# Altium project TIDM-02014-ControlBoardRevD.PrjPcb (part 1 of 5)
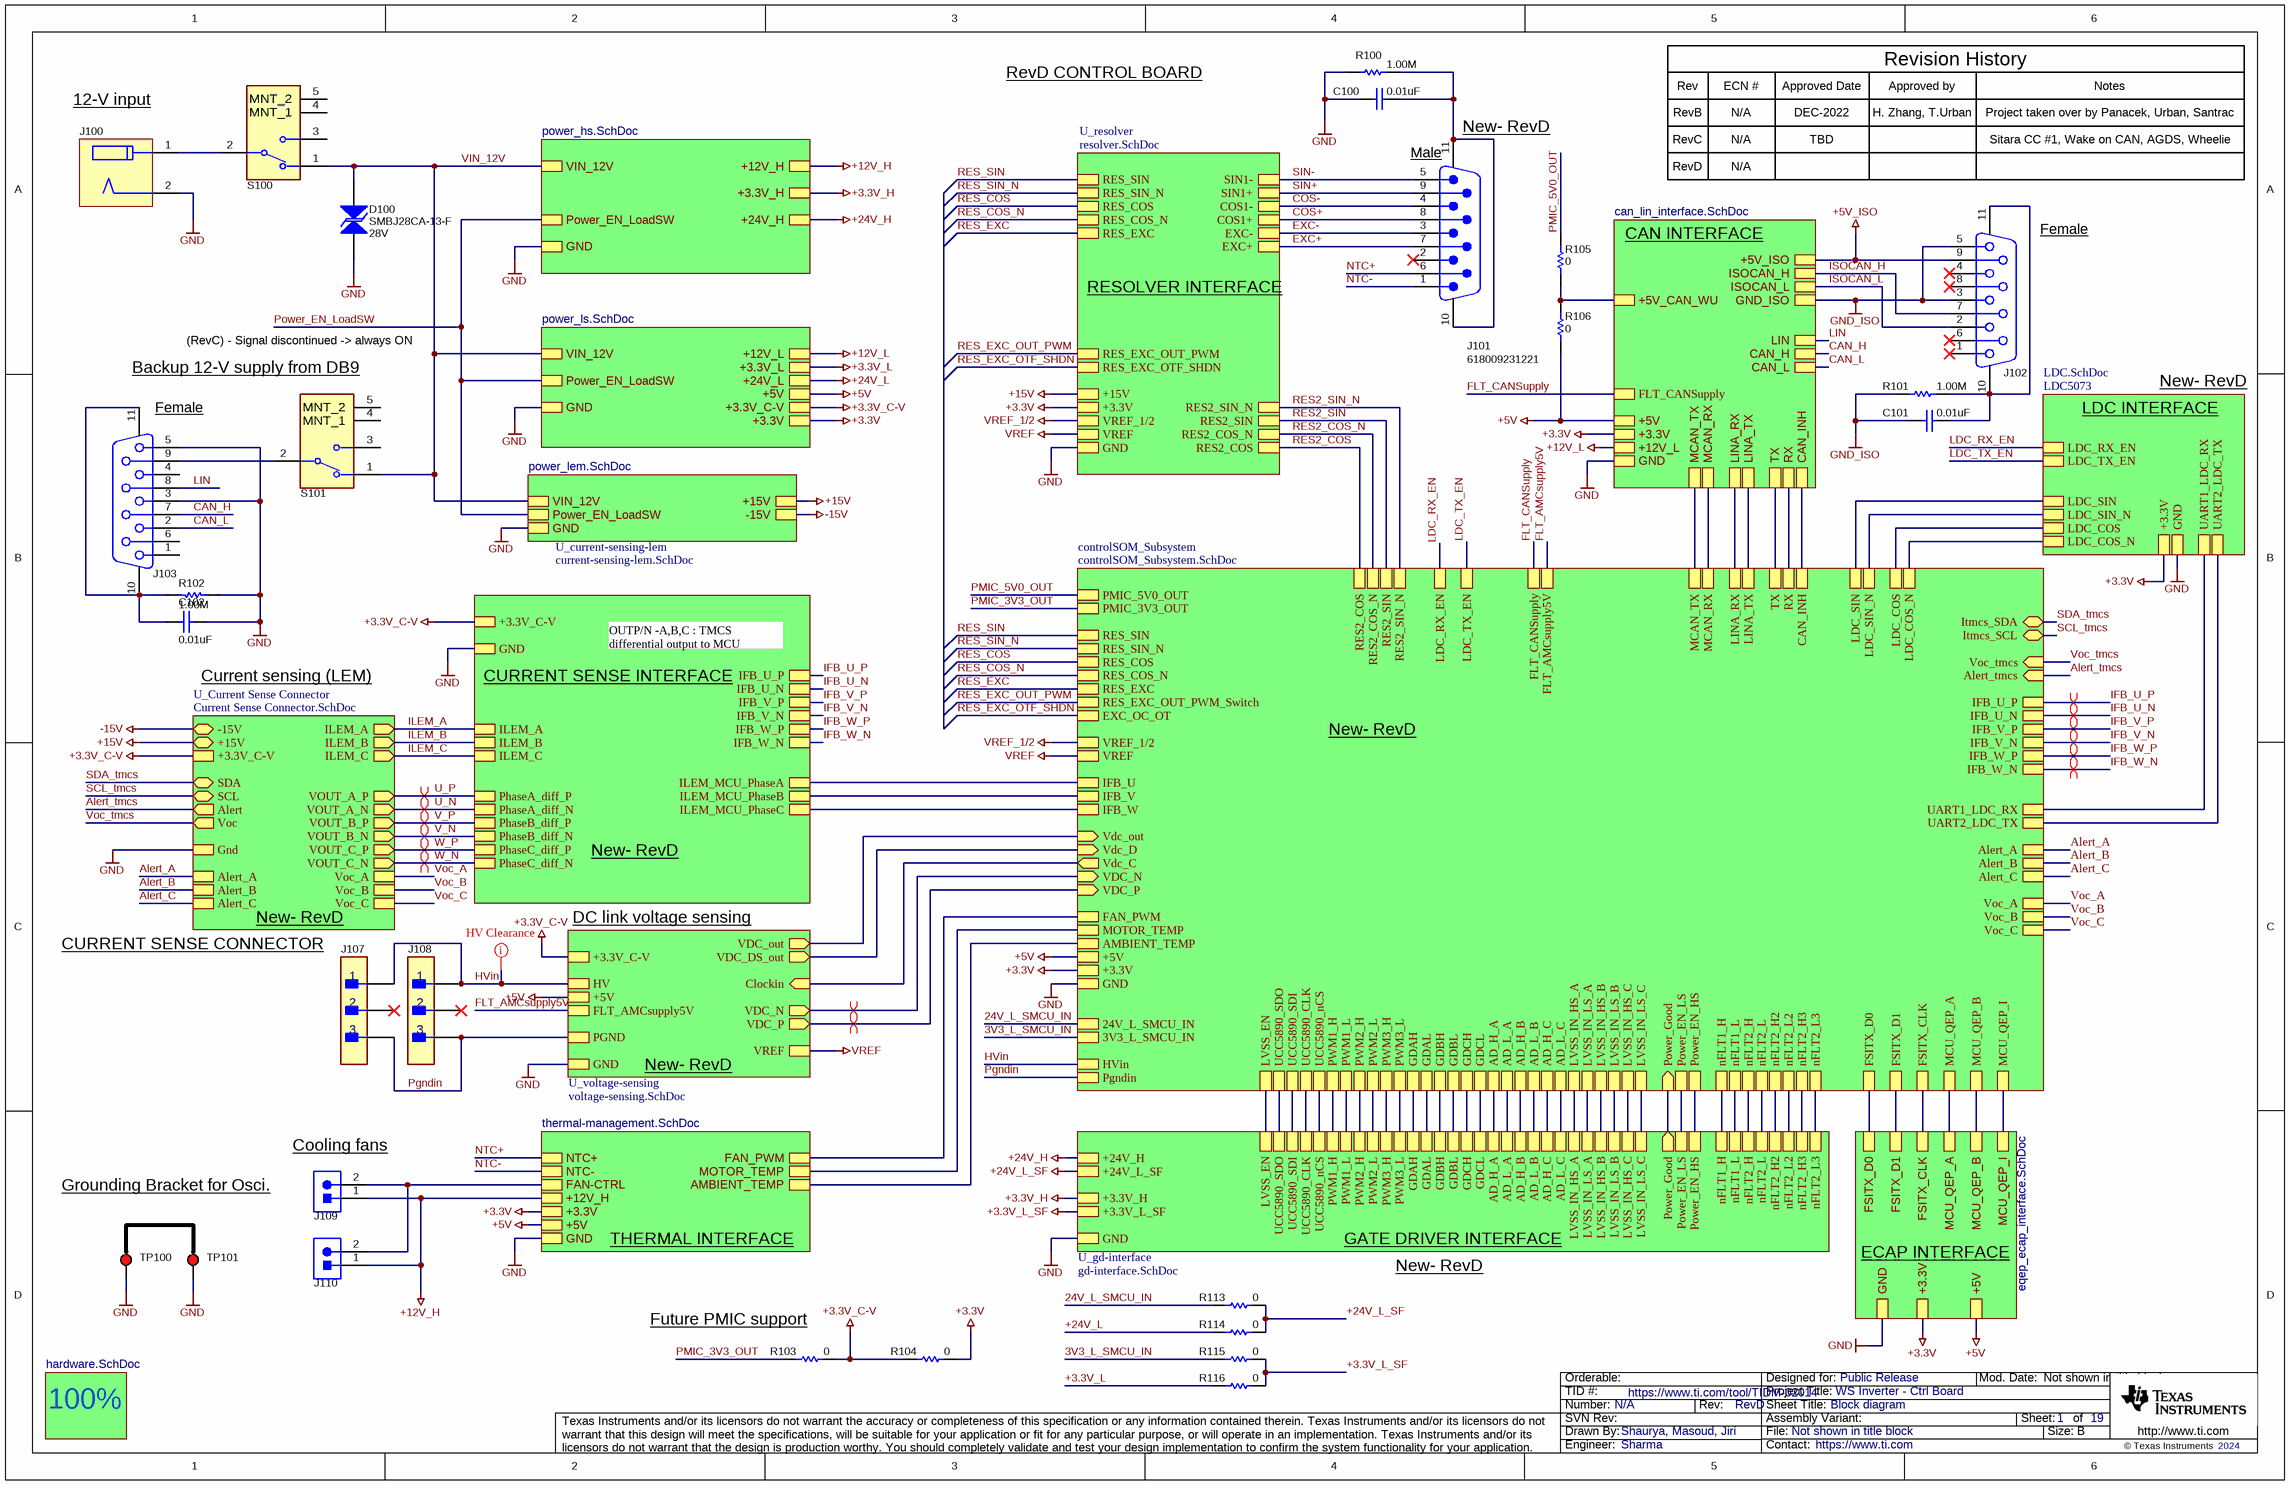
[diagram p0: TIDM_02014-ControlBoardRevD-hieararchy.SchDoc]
CopyrightYear: 2024; PCB_Layout: Sharma; PCB_Rev: RevD; PRJ_Customer: Public Release; PRJ_Engineer: Sharma; PRJ_Number: N/A; PRJ_Title: WS Inverter - Ctrl Board; SCH_Rev: RevD; TechSupport: https://www.ti.com; TID: https://www.ti.com/tool/TIDM-02014
19 sheets, 710 parts. Net scope: strictly hierarchical (ports join the sheet entries above them; power ports are local).
Board file: WS-inverter-control-brd-RevD-SEM.PcbDoc
Sheets:
  TIDM_02014-ControlBoardRevD-hieararchy.SchDoc
    Designator = power_hs.SchDoc
    Designator = power_ls.SchDoc
    Designator = power_lem.SchDoc
    Designator = can_lin_interface.SchDoc
    Designator = thermal-management.SchDoc
    Designator = hardware.SchDoc
    Designator = eqep_ecap_interface.SchDoc
    U_Current Sense Connector = Current Sense Connector.SchDoc
    U_gd-interface = gd-interface.SchDoc
    controlSOM_Subsystem = controlSOM_Subsystem.SchDoc
      Safety MCU = Safety MCU.SchDoc
      Safe State Behavior Settings = Safe State Behavior Settings.SchDoc
    U_voltage-sensing = voltage-sensing.SchDoc
      U_Voltage-sense-LVside = Voltage-sense-LVside.SchDoc
    U_current-sensing-lem = current-sensing-lem.SchDoc
      Phase A = current-sense-lem-new.SchDoc
      Phase C = current-sense-lem-new.SchDoc
      Phase B = current-sense-lem-new.SchDoc
    U_resolver = resolver.SchDoc
    LDC5073 = LDC.SchDoc

## Sheet TIDM_02014-ControlBoardRevD-hieararchy.SchDoc: Block diagram
size 431 x 279 mm; Date: Not shown in title block; ApprovedBy: Not shown in title block; CheckedBy: Not shown in title block; Author: Not shown in title block; CompanyName: Not shown in title block; DrawnBy: Shaurya, Masoud, Jiri; Engineer: Shaurya Sharma; Organization: SEM HEV/EV Traction Inverter; Address1: Not shown in title block; Address2: Not shown in title block; Address3: Not shown in title block; Address4: Not shown in title block; DocumentNumber: 1; Revision: RevD; SheetNumber: 1; SheetTotal: 19; PageSetup: Record=PageOptions¦CenterHorizontal=True¦CenterVertical=True¦PrintScale=0.69¦XCorrection=1.00¦YCorrection=1.00¦PrintKind=0¦BorderSize=5000000¦LeftOffset=0¦BottomOffset=0¦Orientation=2¦PaperLength=1000¦PaperWidth=1000¦Scale=100¦PaperSource=15¦PrintQuality=600¦MediaType=1¦DitherType=10¦PaperKind=Letter¦PrintScaleMode=1

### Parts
C100  ValueDisplayed: 0.01uF  [1206]  (hidden comment: 12061C103JAT2A)
C101  ValueDisplayed: 0.01uF  [1206]  (hidden comment: 12061C103JAT2A)
C102  ValueDisplayed: 0.01uF  [1206]  (hidden comment: 12061C103JAT2A)
D100  SMBJ28CA-13-F  value 28V  [SMB-Bi]
J100  PJ-037AH  [CUI_PJ-037AH]  (value not drawn)
J101  618009231221  [FP-618009231221_CONN_DSUB_30MM8_18MM4-MFG]
J102  618009231121  [Wurth_618009231121]  (value not drawn)
J103  618009231121  [Wurth_618009231121]  (value not drawn)
J107  HPM-03-01-T-S  [FP-HPM-03-01-T-S_HDR3-MFG]  (value not drawn)
J108  HPM-03-01-T-S  [FP-HPM-03-01-T-S_HDR3-MFG]  (value not drawn)
J109  640456-2  [TE_640456-2]  (value not drawn)
J110  640456-2  [TE_640456-2]  (value not drawn)
R100  ValueDisplayed: 1.00M  [0603]  (hidden comment: CRCW06031M00FKEA)
R101  ValueDisplayed: 1.00M  [0603]  (hidden comment: CRCW06031M00FKEA)
R102  ValueDisplayed: 1.00M  [0603]  (hidden comment: CRCW06031M00FKEA)
R103  ValueDisplayed: 0  [5106]  (hidden comment: 5106)
R104  ValueDisplayed: 0  [5106]  (hidden comment: 5106)
R105  ValueDisplayed: 0  [5106]  (hidden comment: 5106)
R106  ValueDisplayed: 0  [5106]  (hidden comment: 5106)
R113  ValueDisplayed: 0  [5106]  (hidden comment: 5106)
R114  ValueDisplayed: 0  [5106]  (hidden comment: 5106)
R115  ValueDisplayed: 0  [5106]  (hidden comment: 5106)
R116  ValueDisplayed: 0  [5106]  (hidden comment: 5106)
S100  200MSP1T1B2M6QE  [FP-200MSP1T1B2M6QE_PTH_SW_23MM63_8MM13-MFG]  (value not drawn)
S101  200MSP1T1B2M6QE  [FP-200MSP1T1B2M6QE_PTH_SW_23MM63_8MM13-MFG]  (value not drawn)
TP100  5000  [Keystone5000]  (value not drawn)
TP101  5000  [Keystone5000]  (value not drawn)

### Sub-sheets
controlSOM_Subsystem = controlSOM_Subsystem.SchDoc: RES_EXC_OUT_PWM_Switch, IFB_V, IFB_W, VREF_1/2, PWM2_H, PWM2_L, PWM1_H, PWM1_L, PWM3_H, PWM3_L, nFLT1_L, LVSS_EN, UCC5890_SDO, UCC5890_CLK, UCC5890_nCS, Power_Good (in), Power_EN_LS, MCAN_TX, MCAN_RX, LINA_RX, LINA_TX, TX, RX, +3.3V, AMBIENT_TEMP, IFB_U, +5V, GND, FSITX_D0, FSITX_D1, FSITX_CLK, EXC_OC_OT, RES_COS, VREF, Power_EN_HS, GDAH, GDAL, LVSS_IN_HS_A, LVSS_IN_LS_A, AD_H_B, AD_H_C, AD_H_A, LVSS_IN_HS_C, LVSS_IN_HS_B, LVSS_IN_LS_B, LVSS_IN_LS_C, AD_L_A, AD_L_B, AD_L_C, GDBH, GDBL, GDCL, GDCH, nFLT2_L, CAN_INH, PMIC_5V0_OUT, PMIC_3V3_OUT, RES_SIN, MOTOR_TEMP, RES_EXC, MCU_QEP_A, MCU_QEP_B, MCU_QEP_I, FAN_PWM, RES2_COS, RES2_COS_N, RES2_SIN, RES2_SIN_N, RES_SIN_N, RES_COS_N, Vdc_out (in), VDC_P (in), Vdc_D (in), Vdc_C (out), IFB_U_P, IFB_U_N, IFB_V_P, IFB_V_N, IFB_W_P, IFB_W_N, nFLT2_H2, nFLT2_L2, nFLT2_H3, nFLT2_L3, nFLT1_H, UCC5890_SDI, Itmcs_SDA (bidir), Itmcs_SCL (bidir), Voc_tmcs (in), Alert_tmcs (in), VDC_N (in), nFLT2_H, Alert_A, Alert_B, Alert_C, Voc_A, Voc_B, Voc_C, LDC_SIN, LDC_SIN_N, LDC_COS, LDC_COS_N, UART1_LDC_RX, UART2_LDC_TX, LDC_RX_EN, LDC_TX_EN, FLT_CANSupply, FLT_AMCsupply5V, HVin, Pgndin, 24V_L_SMCU_IN, 3V3_L_SMCU_IN
Designator = power_hs.SchDoc: VIN_12V, GND, Power_EN_LoadSW, +12V_H, +3.3V_H, +24V_H
Designator = power_ls.SchDoc: VIN_12V, GND, Power_EN_LoadSW, +12V_L, +3.3V_L, +24V_L, +5V, +3.3V_C-V, +3.3V
Designator = power_lem.SchDoc: VIN_12V, GND, Power_EN_LoadSW, +15V, -15V
Designator = can_lin_interface.SchDoc: GND_ISO, ISOCAN_L, MCAN_TX, MCAN_RX, LINA_RX, LINA_TX, LIN, TX, RX, CAN_H, CAN_L, +5V, +3.3V, GND, ISOCAN_H, +5V_ISO, CAN_INH, +12V_L, +5V_CAN_WU, FLT_CANSupply
Designator = thermal-management.SchDoc: NTC+, NTC-, +3.3V, GND, MOTOR_TEMP, AMBIENT_TEMP, +5V, FAN-CTRL, +12V_H, FAN_PWM
Designator = hardware.SchDoc: no entries
Designator = eqep_ecap_interface.SchDoc: +3.3V, FSITX_D0, MCU_QEP_A, MCU_QEP_B, MCU_QEP_I, GND, +5V, FSITX_D1, FSITX_CLK
LDC5073 = LDC.SchDoc: LDC_SIN, LDC_SIN_N, LDC_COS, LDC_COS_N, UART1_LDC_RX, UART2_LDC_TX, GND, +3.3V, LDC_RX_EN, LDC_TX_EN
U_Current Sense Connector = Current Sense Connector.SchDoc: -15V (bidir), +15V (bidir), Gnd, ILEM_A (out), ILEM_B (out), ILEM_C (out), +3.3V_C-V, SDA (bidir), SCL (bidir), Alert (out), Voc (out), VOUT_A_P (out), VOUT_A_N (out), VOUT_B_P (out), VOUT_B_N (out), VOUT_C_P (out), VOUT_C_N (out), Voc_B, Voc_C, Voc_A, Alert_A, Alert_B, Alert_C
U_current-sensing-lem = current-sensing-lem.SchDoc: GND, +3.3V_C-V, IFB_U_P, IFB_V_P, IFB_W_P, IFB_U_N, IFB_V_N, IFB_W_N, ILEM_B, ILEM_C, ILEM_A, PhaseC_diff_N, PhaseC_diff_P, ILEM_MCU_PhaseC, PhaseA_diff_N, PhaseA_diff_P, ILEM_MCU_PhaseA, PhaseB_diff_N, PhaseB_diff_P, ILEM_MCU_PhaseB
U_gd-interface = gd-interface.SchDoc: +3.3V_H, GND, +3.3V_L_SF, UCC5890_SDI, UCC5890_nCS, +24V_H, +24V_L_SF, UCC5890_SDO, UCC5890_CLK, PWM1_L, PWM1_H, nFLT1_H, nFLT2_H, nFLT1_L, nFLT2_L, Power_EN_HS, Power_EN_LS, LVSS_EN, LVSS_IN_LS_A, LVSS_IN_HS_A, GDAL, GDAH, PWM2_L, PWM2_H, PWM3_H, PWM3_L, AD_L_A, AD_H_A, AD_L_B, AD_H_B, LVSS_IN_LS_B, GDBH, GDBL, LVSS_IN_HS_B, LVSS_IN_HS_C, GDCH, GDCL, AD_L_C, AD_H_C, LVSS_IN_LS_C, Power_Good (out), nFLT2_H2, nFLT2_H3, nFLT2_L2, nFLT2_L3
U_resolver = resolver.SchDoc: SIN1+, SIN1-, COS1+, COS1-, RES_SIN, RES_COS, GND, RES_EXC, +3.3V, +15V, EXC+, RES_EXC_OUT_PWM, EXC-, RES_EXC_OTF_SHDN, VREF_1/2, VREF, RES2_COS, RES2_COS_N, RES2_SIN, RES2_SIN_N, RES_SIN_N, RES_COS_N
U_voltage-sensing = voltage-sensing.SchDoc: GND, VDC_out (out), PGND, HV, VDC_P (out), +3.3V_C-V, VDC_DS_out (out), Clockin (in), VDC_N (out), VREF, +5V, FLT_AMCsupply5V

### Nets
3V3_L_SMCU_IN: R115.2 ; sheet controlSOM_Subsystem/3V3_L_SMCU_IN
24V_L_SMCU_IN: R113.2 ; sheet controlSOM_Subsystem/24V_L_SMCU_IN
+3.3V: R104.1 ; sheet Designator/+3.3V, sheet Designator/+3.3V, sheet Designator/+3.3V, sheet Designator/+3.3V, sheet controlSOM_Subsystem/+3.3V, sheet U_resolver/+3.3V, sheet LDC5073/+3.3V
+3.3V_C-V: R103.1 R104.2 ; sheet Designator/+3.3V_C-V, sheet U_Current Sense Connector/+3.3V_C-V, sheet U_voltage-sensing/+3.3V_C-V, sheet U_current-sensing-lem/+3.3V_C-V
+3.3V_H: sheet Designator/+3.3V_H, sheet U_gd-interface/+3.3V_H
+3.3V_L: R116.2 ; sheet Designator/+3.3V_L
+3.3V_L_SF: R115.1 R116.1 ; sheet U_gd-interface/+3.3V_L_SF
+5V: R106.1 ; sheet Designator/+5V, sheet Designator/+5V, sheet Designator/+5V, sheet Designator/+5V, sheet controlSOM_Subsystem/+5V, sheet U_voltage-sensing/+5V
+5V_CAN_WU: R105.2 R106.2 ; sheet Designator/+5V_CAN_WU
+5V_ISO: J102.9 ; sheet Designator/+5V_ISO
+12V_H: J109.1 J110.1 ; sheet Designator/+12V_H, sheet Designator/+12V_H
+12V_L: sheet Designator/+12V_L, sheet Designator/+12V_L
+15V: sheet Designator/+15V, sheet U_Current Sense Connector/+15V, sheet U_resolver/+15V
+24V_H: sheet Designator/+24V_H, sheet U_gd-interface/+24V_H
+24V_L: R114.2 ; sheet Designator/+24V_L
+24V_L_SF: R113.1 R114.1 ; sheet U_gd-interface/+24V_L_SF
-15V: sheet Designator/-15V, sheet U_Current Sense Connector/-15V
GND: C100.2 C102.2 D100.2 J100.2 J103.3 J103.5 R100.1 R102.1 TP100.1 TP101.1 ; sheet Designator/GND, sheet Designator/GND, sheet Designator/GND, sheet Designator/GND, sheet Designator/GND, sheet Designator/GND, sheet U_Current Sense Connector/Gnd, sheet U_gd-interface/GND, sheet controlSOM_Subsystem/GND, sheet U_voltage-sensing/GND, sheet U_current-sensing-lem/GND, sheet U_resolver/GND, sheet LDC5073/GND
GND_ISO: C101.2 J102.3 J102.5 R101.1 ; sheet Designator/GND_ISO
HVin: J107.1 J108.1 ; sheet controlSOM_Subsystem/HVin, sheet U_voltage-sensing/HV  [project net HV]
Pgndin: J107.3 J108.3 ; sheet controlSOM_Subsystem/Pgndin, sheet U_voltage-sensing/PGND
VIN_12V: D100.1 S100.1 S101.1 ; sheet Designator/VIN_12V, sheet Designator/VIN_12V, sheet Designator/VIN_12V
VREF: sheet controlSOM_Subsystem/VREF, sheet U_voltage-sensing/VREF, sheet U_resolver/VREF
VREF_1/2: sheet controlSOM_Subsystem/VREF_1/2, sheet U_resolver/VREF_1/2
AD_H_A: sheet U_gd-interface/AD_H_A, sheet controlSOM_Subsystem/AD_H_A
AD_H_B: sheet U_gd-interface/AD_H_B, sheet controlSOM_Subsystem/AD_H_B
AD_H_C: sheet U_gd-interface/AD_H_C, sheet controlSOM_Subsystem/AD_H_C
AD_L_A: sheet U_gd-interface/AD_L_A, sheet controlSOM_Subsystem/AD_L_A
AD_L_B: sheet U_gd-interface/AD_L_B, sheet controlSOM_Subsystem/AD_L_B
AD_L_C: sheet U_gd-interface/AD_L_C, sheet controlSOM_Subsystem/AD_L_C
Alert_A: sheet U_Current Sense Connector/Alert_A, sheet controlSOM_Subsystem/Alert_A
Alert_B: sheet U_Current Sense Connector/Alert_B, sheet controlSOM_Subsystem/Alert_B
Alert_C: sheet U_Current Sense Connector/Alert_C, sheet controlSOM_Subsystem/Alert_C
Alert_tmcs: sheet U_Current Sense Connector/Alert, sheet controlSOM_Subsystem/Alert_tmcs
AMBIENT_TEMP: sheet Designator/AMBIENT_TEMP, sheet controlSOM_Subsystem/AMBIENT_TEMP
CAN_H: J103.7 ; sheet Designator/CAN_H
CAN_INH: sheet Designator/CAN_INH, sheet controlSOM_Subsystem/CAN_INH
CAN_L: J103.2 ; sheet Designator/CAN_L
COS+: J101.8 ; sheet U_resolver/COS1+
COS-: J101.4 ; sheet U_resolver/COS1-
EXC+: J101.7 ; sheet U_resolver/EXC+
EXC-: J101.3 ; sheet U_resolver/EXC-
FAN-CTRL: J109.2 J110.2 ; sheet Designator/FAN-CTRL
FAN_PWM: sheet Designator/FAN_PWM, sheet controlSOM_Subsystem/FAN_PWM
FLT_AMCsupply5V: sheet controlSOM_Subsystem/FLT_AMCsupply5V, sheet U_voltage-sensing/FLT_AMCsupply5V
FLT_CANSupply: sheet Designator/FLT_CANSupply, sheet controlSOM_Subsystem/FLT_CANSupply
FSITX_CLK: sheet Designator/FSITX_CLK, sheet controlSOM_Subsystem/FSITX_CLK
FSITX_D0: sheet Designator/FSITX_D0, sheet controlSOM_Subsystem/FSITX_D0
FSITX_D1: sheet Designator/FSITX_D1, sheet controlSOM_Subsystem/FSITX_D1
GDAH: sheet U_gd-interface/GDAH, sheet controlSOM_Subsystem/GDAH
GDAL: sheet U_gd-interface/GDAL, sheet controlSOM_Subsystem/GDAL
GDBH: sheet U_gd-interface/GDBH, sheet controlSOM_Subsystem/GDBH
GDBL: sheet U_gd-interface/GDBL, sheet controlSOM_Subsystem/GDBL
GDCH: sheet U_gd-interface/GDCH, sheet controlSOM_Subsystem/GDCH
GDCL: sheet U_gd-interface/GDCL, sheet controlSOM_Subsystem/GDCL
IFB_U: sheet controlSOM_Subsystem/IFB_U, sheet U_current-sensing-lem/ILEM_MCU_PhaseA
IFB_U_N: sheet controlSOM_Subsystem/IFB_U_N, sheet U_current-sensing-lem/IFB_U_N
IFB_U_P: sheet controlSOM_Subsystem/IFB_U_P, sheet U_current-sensing-lem/IFB_U_P
IFB_V: sheet controlSOM_Subsystem/IFB_V, sheet U_current-sensing-lem/ILEM_MCU_PhaseB
IFB_V_N: sheet controlSOM_Subsystem/IFB_V_N, sheet U_current-sensing-lem/IFB_V_N
IFB_V_P: sheet controlSOM_Subsystem/IFB_V_P, sheet U_current-sensing-lem/IFB_V_P
IFB_W: sheet controlSOM_Subsystem/IFB_W, sheet U_current-sensing-lem/ILEM_MCU_PhaseC
IFB_W_N: sheet controlSOM_Subsystem/IFB_W_N, sheet U_current-sensing-lem/IFB_W_N
IFB_W_P: sheet controlSOM_Subsystem/IFB_W_P, sheet U_current-sensing-lem/IFB_W_P
ILEM_A: sheet U_Current Sense Connector/ILEM_A, sheet U_current-sensing-lem/ILEM_A
ILEM_B: sheet U_Current Sense Connector/ILEM_B, sheet U_current-sensing-lem/ILEM_B
ILEM_C: sheet U_Current Sense Connector/ILEM_C, sheet U_current-sensing-lem/ILEM_C  [project net ILEM_B]
ISOCAN_H: J102.7 ; sheet Designator/ISOCAN_H
ISOCAN_L: J102.2 ; sheet Designator/ISOCAN_L
LDC_COS: sheet controlSOM_Subsystem/LDC_COS, sheet LDC5073/LDC_COS
LDC_COS_N: sheet controlSOM_Subsystem/LDC_COS_N, sheet LDC5073/LDC_COS_N
LDC_RX_EN: sheet controlSOM_Subsystem/LDC_RX_EN, sheet LDC5073/LDC_RX_EN
LDC_SIN: sheet controlSOM_Subsystem/LDC_SIN, sheet LDC5073/LDC_SIN
LDC_SIN_N: sheet controlSOM_Subsystem/LDC_SIN_N, sheet LDC5073/LDC_SIN_N
LDC_TX_EN: sheet controlSOM_Subsystem/LDC_TX_EN, sheet LDC5073/LDC_TX_EN
LIN: J103.8 ; sheet Designator/LIN
LINA_RX: sheet Designator/LINA_RX, sheet controlSOM_Subsystem/LINA_RX
LINA_TX: sheet Designator/LINA_TX, sheet controlSOM_Subsystem/LINA_TX
LVSS_EN: sheet U_gd-interface/LVSS_EN, sheet controlSOM_Subsystem/LVSS_EN
LVSS_IN_HS_A: sheet U_gd-interface/LVSS_IN_HS_A, sheet controlSOM_Subsystem/LVSS_IN_HS_A
LVSS_IN_HS_B: sheet U_gd-interface/LVSS_IN_HS_B, sheet controlSOM_Subsystem/LVSS_IN_HS_B
LVSS_IN_HS_C: sheet U_gd-interface/LVSS_IN_HS_C, sheet controlSOM_Subsystem/LVSS_IN_HS_C
LVSS_IN_LS_A: sheet U_gd-interface/LVSS_IN_LS_A, sheet controlSOM_Subsystem/LVSS_IN_LS_A
LVSS_IN_LS_B: sheet U_gd-interface/LVSS_IN_LS_B, sheet controlSOM_Subsystem/LVSS_IN_LS_B
LVSS_IN_LS_C: sheet U_gd-interface/LVSS_IN_LS_C, sheet controlSOM_Subsystem/LVSS_IN_LS_C
MCAN_RX: sheet Designator/MCAN_RX, sheet controlSOM_Subsystem/MCAN_RX
MCAN_TX: sheet Designator/MCAN_TX, sheet controlSOM_Subsystem/MCAN_TX
MCU_QEP_A: sheet Designator/MCU_QEP_A, sheet controlSOM_Subsystem/MCU_QEP_A
MCU_QEP_B: sheet Designator/MCU_QEP_B, sheet controlSOM_Subsystem/MCU_QEP_B
MCU_QEP_I: sheet Designator/MCU_QEP_I, sheet controlSOM_Subsystem/MCU_QEP_I
MOTOR_TEMP: sheet Designator/MOTOR_TEMP, sheet controlSOM_Subsystem/MOTOR_TEMP
nFLT1_H: sheet U_gd-interface/nFLT1_H, sheet controlSOM_Subsystem/nFLT1_H
nFLT1_L: sheet U_gd-interface/nFLT1_L, sheet controlSOM_Subsystem/nFLT1_L
nFLT2_H: sheet U_gd-interface/nFLT2_H, sheet controlSOM_Subsystem/nFLT2_H
nFLT2_H2: sheet U_gd-interface/nFLT2_H2, sheet controlSOM_Subsystem/nFLT2_H2
nFLT2_H3: sheet U_gd-interface/nFLT2_H3, sheet controlSOM_Subsystem/nFLT2_H3
nFLT2_L: sheet U_gd-interface/nFLT2_L, sheet controlSOM_Subsystem/nFLT2_L
nFLT2_L2: sheet U_gd-interface/nFLT2_L2, sheet controlSOM_Subsystem/nFLT2_L2
nFLT2_L3: sheet U_gd-interface/nFLT2_L3, sheet controlSOM_Subsystem/nFLT2_L3
NTC+: J101.6 ; sheet Designator/NTC+
NTC-: J101.1 ; sheet Designator/NTC-
PMIC_3V3_OUT: R103.2 ; sheet controlSOM_Subsystem/PMIC_3V3_OUT
PMIC_5V0_OUT: R105.1 ; sheet controlSOM_Subsystem/PMIC_5V0_OUT
Power_EN_HS: sheet U_gd-interface/Power_EN_HS, sheet controlSOM_Subsystem/Power_EN_HS
Power_EN_LoadSW: sheet Designator/Power_EN_LoadSW, sheet Designator/Power_EN_LoadSW, sheet Designator/Power_EN_LoadSW
Power_EN_LS: sheet U_gd-interface/Power_EN_LS, sheet controlSOM_Subsystem/Power_EN_LS
Power_good: sheet U_gd-interface/Power_Good, sheet controlSOM_Subsystem/Power_Good
PWM1_H: sheet U_gd-interface/PWM1_H, sheet controlSOM_Subsystem/PWM1_H
PWM1_L: sheet U_gd-interface/PWM1_L, sheet controlSOM_Subsystem/PWM1_L
PWM2_H: sheet U_gd-interface/PWM2_H, sheet controlSOM_Subsystem/PWM2_H
PWM2_L: sheet U_gd-interface/PWM2_L, sheet controlSOM_Subsystem/PWM2_L
PWM3_H: sheet U_gd-interface/PWM3_H, sheet controlSOM_Subsystem/PWM3_H
PWM3_L: sheet U_gd-interface/PWM3_L, sheet controlSOM_Subsystem/PWM3_L
RES2_COS: sheet controlSOM_Subsystem/RES2_COS, sheet U_resolver/RES2_COS
RES2_COS_N: sheet controlSOM_Subsystem/RES2_COS_N, sheet U_resolver/RES2_COS_N
RES2_SIN: sheet controlSOM_Subsystem/RES2_SIN, sheet U_resolver/RES2_SIN
RES2_SIN_N: sheet controlSOM_Subsystem/RES2_SIN_N, sheet U_resolver/RES2_SIN_N
RES_COS: sheet controlSOM_Subsystem/RES_COS, sheet U_resolver/RES_COS
RES_COS_N: sheet controlSOM_Subsystem/RES_COS_N, sheet U_resolver/RES_COS_N
RES_EXC: sheet controlSOM_Subsystem/RES_EXC, sheet U_resolver/RES_EXC
RES_EXC_OTF_SHDN: sheet controlSOM_Subsystem/EXC_OC_OT, sheet U_resolver/RES_EXC_OTF_SHDN  [project net EXC_OC_OT]
RES_EXC_OUT_PWM: sheet controlSOM_Subsystem/RES_EXC_OUT_PWM_Switch, sheet U_resolver/RES_EXC_OUT_PWM
RES_SIN: sheet controlSOM_Subsystem/RES_SIN, sheet U_resolver/RES_SIN
RES_SIN_N: sheet controlSOM_Subsystem/RES_SIN_N, sheet U_resolver/RES_SIN_N
RX: sheet Designator/RX, sheet controlSOM_Subsystem/RX
SCL_tmcs: sheet U_Current Sense Connector/SCL, sheet controlSOM_Subsystem/Itmcs_SCL  [project net IFB_I2C_SCL]
SDA_tmcs: sheet U_Current Sense Connector/SDA, sheet controlSOM_Subsystem/Itmcs_SDA  [project net IFB_I2C_SDA]
SIN+: J101.9 ; sheet U_resolver/SIN1+
SIN-: J101.5 ; sheet U_resolver/SIN1-
TX: sheet Designator/TX, sheet controlSOM_Subsystem/TX
U_N: sheet U_Current Sense Connector/VOUT_A_N, sheet U_current-sensing-lem/PhaseA_diff_N
U_P: sheet U_Current Sense Connector/VOUT_A_P, sheet U_current-sensing-lem/PhaseA_diff_P
UART1_LDC_RX: sheet controlSOM_Subsystem/UART1_LDC_RX, sheet LDC5073/UART1_LDC_RX
UART2_LDC_TX: sheet controlSOM_Subsystem/UART2_LDC_TX, sheet LDC5073/UART2_LDC_TX
UCC5890_CLK: sheet U_gd-interface/UCC5890_CLK, sheet controlSOM_Subsystem/UCC5890_CLK
UCC5890_nCS: sheet U_gd-interface/UCC5890_nCS, sheet controlSOM_Subsystem/UCC5890_nCS
UCC5890_SDI: sheet U_gd-interface/UCC5890_SDI, sheet controlSOM_Subsystem/UCC5890_SDI
UCC5890_SDO: sheet U_gd-interface/UCC5890_SDO, sheet controlSOM_Subsystem/UCC5890_SDO
V_N: sheet U_Current Sense Connector/VOUT_B_N, sheet U_current-sensing-lem/PhaseB_diff_N
V_P: sheet U_Current Sense Connector/VOUT_B_P, sheet U_current-sensing-lem/PhaseB_diff_P
VDC: sheet controlSOM_Subsystem/Vdc_out, sheet U_voltage-sensing/VDC_out
Vdc_C: sheet controlSOM_Subsystem/Vdc_C, sheet U_voltage-sensing/Clockin
Vdc_D: sheet controlSOM_Subsystem/Vdc_D, sheet U_voltage-sensing/VDC_DS_out
VDC_N: sheet controlSOM_Subsystem/VDC_N, sheet U_voltage-sensing/VDC_N
VDC_P: sheet controlSOM_Subsystem/VDC_P, sheet U_voltage-sensing/VDC_P
Voc_A: sheet U_Current Sense Connector/Voc_A, sheet controlSOM_Subsystem/Voc_A  [project net IFB_VOC_U]
Voc_B: sheet U_Current Sense Connector/Voc_B, sheet controlSOM_Subsystem/Voc_B  [project net IFB_VOC_W]
Voc_C: sheet U_Current Sense Connector/Voc_C, sheet controlSOM_Subsystem/Voc_C  [project net IFB_VOC_V]
Voc_tmcs: sheet U_Current Sense Connector/Voc, sheet controlSOM_Subsystem/Voc_tmcs
W_N: sheet U_Current Sense Connector/VOUT_C_N, sheet U_current-sensing-lem/PhaseC_diff_N  [project net VOUT_C_N]
W_P: sheet U_Current Sense Connector/VOUT_C_P, sheet U_current-sensing-lem/PhaseC_diff_P  [project net VOUT_C_P]
NetC100_1: C100.1 J101.10 J101.11 R100.2
NetC101_1: C101.1 J102.10 J102.11 R101.2
NetC102_1: C102.1 J103.10 J103.11 R102.2
NetJ100_1: J100.1 S100.2(Comm.)
NetJ103_9: J103.9 S101.2(Comm.)

Not connected (* = marked no-connect by the designer): J101 2*; J102 1* 4* 6* 8*; J103 1 4 6; J107 2*; J108 2*; S100 3 4(MNT_1) 5(MNT_2); S101 3 4(MNT_1) 5(MNT_2)

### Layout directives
net class HVC: HV
differential pair: IFB_U_N, IFB_U_P, IFB_V_N, IFB_V_P, IFB_W_N, IFB_W_P, U_N, U_P, V_N, V_P, VDC_N, VDC_P, VOUT_C_N, VOUT_C_P

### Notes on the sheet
- (near J100) 12-V input
- RevD CONTROL BOARD
- Rev
- ECN #
- Approved Date
- Approved by
- Revision History
- Notes
- (near J101) Male
- (near J101) New- RevD
- RevB
- RevC
- RevD
- N/A
- DEC-2022
- TBD
- H. Zhang, T.Urban
- Project taken over by Panacek, Urban, Santrac
- Sitara CC #1, Wake on CAN, AGDS, Wheelie
- CAN INTERFACE
- (near J102) Female
- RESOLVER INTERFACE
- (near S101) Backup 12-V supply from DB9
- (RevC) - Signal discontinued -> always ON
- (near J103) Female
- LDC INTERFACE
- New- RevD
- (near C102) Current sensing (LEM)
- CURRENT SENSE INTERFACE
- OUTP/N -A,B,C : TMCS differential output to MCU
- CURRENT SENSE CONNECTOR
- DC link voltage sensing
- (near J109) Cooling fans
- Grounding Bracket for Osci.
- THERMAL INTERFACE
- GATE DRIVER INTERFACE
- ECAP INTERFACE
- (near R103) Future PMIC support
- 100%

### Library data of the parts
C100-C102 = CMP-0008484-2: CAP, CERM, 0.01 uF, 100 V, +/- 5%, X7R, 1206; Manufacturer: AVX; TaMin_C: -55°C; ESR_ohm: 0.119; Polarized: N; SizeAreaWB_mm2: 10.92; Value1: 0.119 ohm; U/M: EA; Value: 0.01uF; TaMax_C: 125°C; SizeZ_mm: 1.35; SizeX_mm: 3.2; SizeY_mm: 1.6; Value2: 100V; SizeArea_mm2: 5.12; Cap_F: 10nF; AEC Category: Q200
D100 = CMP-0006046-3: Diode, TVS, Bi, 28 V, 45.4 Vc, SMB; Manufacturer: Diodes Inc.; Vbr_Min: 31.1V; Vc: 45.4V; Ipp: 13.2A; Vbr_Max: 35.8V; AEC Qualified: N; Ppk: 600W; AEC Category: Q101
J100 = CMP-0075114-1: Power Jack, 2mm, R/A, TH; Manufacturer: CUI Inc.; CNHeader: False; Shrouded: N; Gender: Male; Row_Count: 1; Pitch_mm: 6
J101 = CMP-0097487-2: 9 Position D-Sub Plug, Male Pins Connector; Manufacturer: Würth Elektronik; ContactFinish: Gold; DUT-Pitch_mm: 2.77mm; Voltage_V: 125V; Is Female: no; Conn Orientation: Right Angle; SizeZ_mm: 12.7mm; Current_A: 3A
J102 J103 = CMP-0054820-2: Receptacle, D-Sub, 9 Position, R/A, TH; Manufacturer: Wurth Elektronik; CNHeader: FALSE; Current_A: 3A; Gender: Female; Voltage_V: 125V; Row_Count: 2; Pitch_mm: 2.77; ContactFinish: Gold; CT: TRUE; Cert_UL: Y
J107 J108 = CMP-0093760-1: Connector Header Through Hole 3 position 0.200" (5.08mm); Manufacturer: Samtec; Conn Gender: Male; ContactFinish: Tin,Nickel; AEC Qualified: No; Conn Orientation: Straight; SizeZ_mm: 14.74mm; Row_Count: 1
J109 J110 = CMP-0054970-1: Header, 2.54mm, 2x1, Tin, TH; Manufacturer: TE Connectivity; CNHeader: TRUE; Current_A: 5A; Shrouded: N; Gender: Male; Cert_CSA: Y; Voltage_V: 250V; Row_Count: 1; Pitch_mm: 2.54; CT: FALSE
R100-R102 = CMP-0022138-4: RES, 1.00 M, 1%, 0.1 W, AEC-Q200 Grade 0, 0603; Manufacturer: Vishay-Dale; Power_W: 100mW; TempCo: 100 ppm/C; Value_Code: 1M00; Value: 1.00Meg; EIA_Code: E96; Res_ohm: 1M; SizeX_mm: 1.6; SizeY_mm: 0.8; SizeZ_mm: 1; Value2: 0.1W; SizeArea_mm2: 1.28; AEC Qualified: Y; VDC_V: 75V; AEC Category: Q200; AEC Grade: 0
R103-R106 R113-R116 = CMP-0020833-2: RES, 0, 1%, 0.5 W, 0805; Manufacturer: Keystone; SizeArea_mm2: 2.5; AEC Qualified: N; AEC Category: Q200; Value: 0; SizeZ_mm: 0.84; SizeY_mm: 1.25; Power_W: 500mW; Value2: 0.5W; SizeX_mm: 2; TempCo: ppm/C; U/M: EA
S100 S101 = CMP-0097544-1: Switch Toggle SPDT 3A 120V; Manufacturer: E-Switch; VDC_V: 28V; AEC Qualified: No; Electromechanical Life: 30000Cycles; Coil Resistance_ohm: 20mΩ
TP100 TP101 = CMP-0055137-2: Test Point, Miniature, Red, TH; Manufacturer: Keystone Electronics; CNHeader: FALSE; Green_Lifecycle: Active; Green_REACh: Passed; ContactFinish: Silver; CT: TRUE

## Sheet power_hs.SchDoc: High-Side Power Rail
size 431 x 279 mm; Date: Not shown in title block; ApprovedBy: Not shown in title block; CheckedBy: Not shown in title block; Author: Not shown in title block; CompanyName: Not shown in title block; DrawnBy: Panacek; Engineer: Not shown in title block; Organization: Not shown in title block; Address1: Not shown in title block; Address2: Not shown in title block; Address3: Not shown in title block; Address4: Not shown in title block; DocumentNumber: 2; Revision: Use project parameter SCH_Rev; SheetNumber: 2; SheetTotal: 19; PageSetup: Record=PageOptions¦CenterHorizontal=True¦CenterVertical=True¦PrintScale=1.00¦XCorrection=1.00¦YCorrection=1.00¦PrintKind=0¦BorderSize=5000000¦LeftOffset=0¦BottomOffset=0¦Orientation=2¦PaperLength=1000¦PaperWidth=1000¦Scale=100¦PaperSource=15¦PrintQuality=600¦MediaType=1¦DitherType=10¦PaperKind=Letter¦PrintScaleMode=1
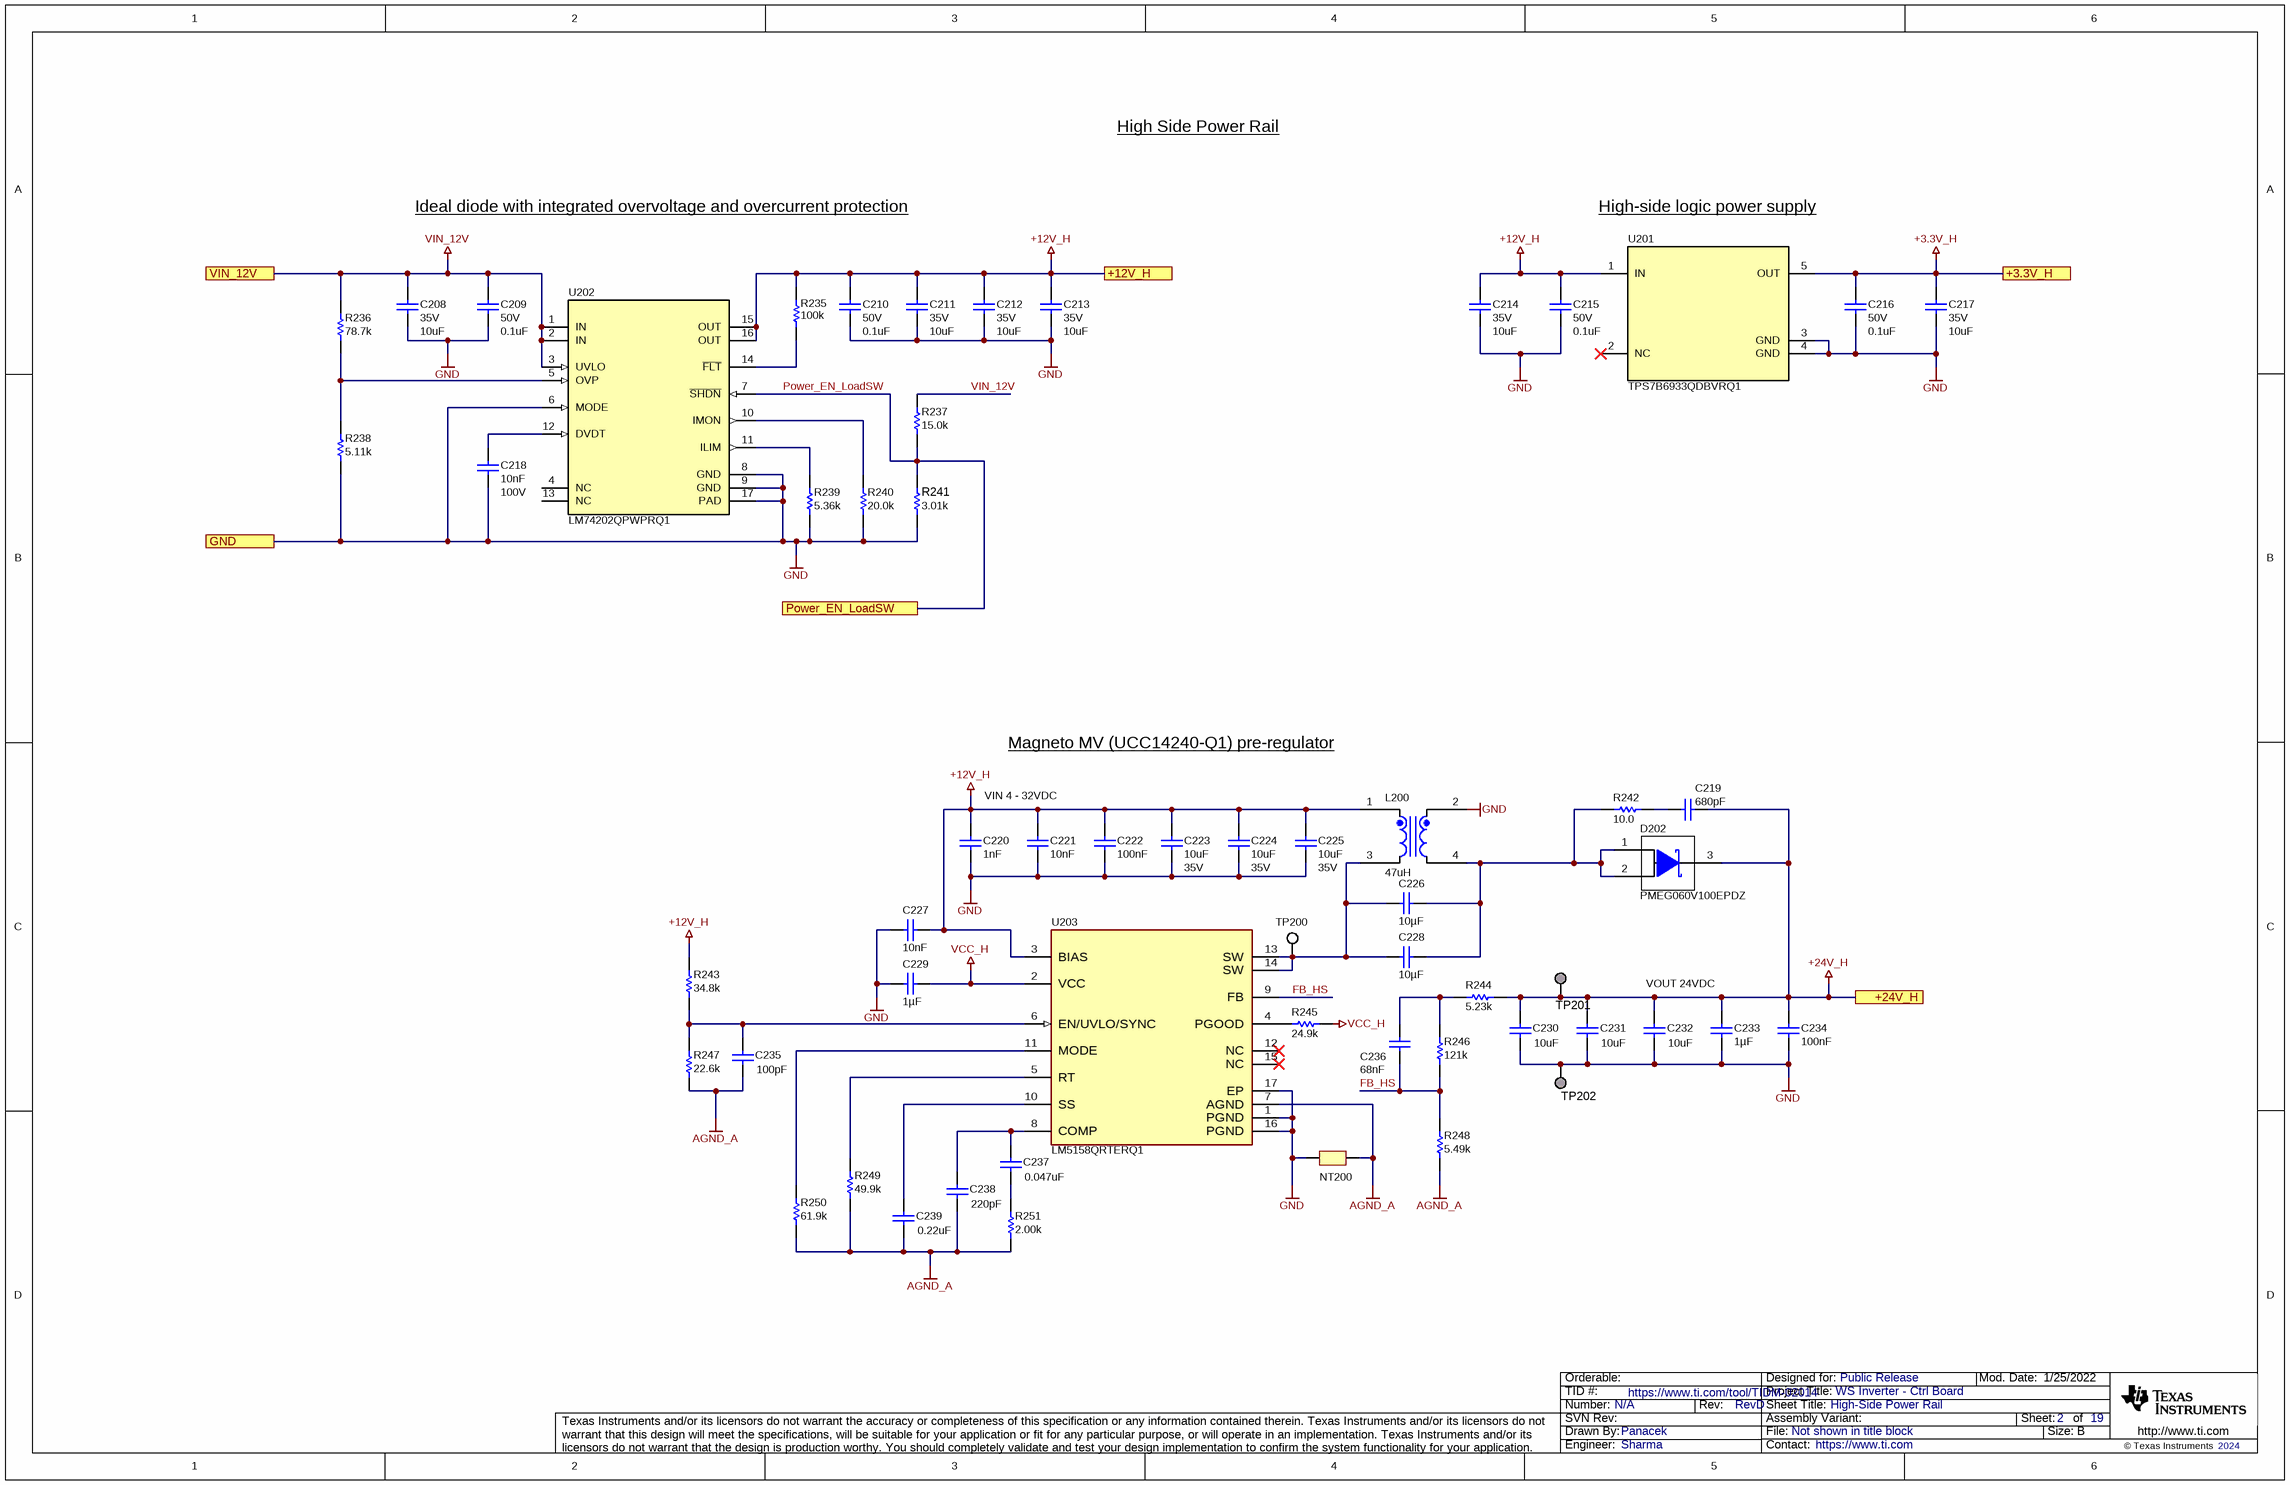
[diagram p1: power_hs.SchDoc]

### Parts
C208  VDC_V: 35V  ValueDisplayed: 10uF  [0603]  (hidden comment: GRM188R6YA106MA73D)
C209  VDC_V: 50V  ValueDisplayed: 0.1uF  [0603]  (hidden comment: CGA3E2X7R1H104K080AA)
C210  VDC_V: 50V  ValueDisplayed: 0.1uF  [0603]  (hidden comment: CGA3E2X7R1H104K080AA)
C211  VDC_V: 35V  ValueDisplayed: 10uF  [0603]  (hidden comment: GRM188R6YA106MA73D)
C212  VDC_V: 35V  ValueDisplayed: 10uF  [0603]  (hidden comment: GRM188R6YA106MA73D)
C213  VDC_V: 35V  ValueDisplayed: 10uF  [0603]  (hidden comment: GRM188R6YA106MA73D)
C214  VDC_V: 35V  ValueDisplayed: 10uF  [0603]  (hidden comment: GRM188R6YA106MA73D)
C215  VDC_V: 50V  ValueDisplayed: 0.1uF  [0603]  (hidden comment: CGA3E2X7R1H104K080AA)
C216  VDC_V: 50V  ValueDisplayed: 0.1uF  [0603]  (hidden comment: CGA3E2X7R1H104K080AA)
C217  VDC_V: 35V  ValueDisplayed: 10uF  [0603]  (hidden comment: GRM188R6YA106MA73D)
C218  Cap_F: 10nF  VDC_V: 100V  [0603]  (hidden comment: CGA3E2X7R2A103K080AA)
C219  ValueDisplayed: 680pF  [0603]  (hidden comment: C0603C681J5GACTU)
C220  Cap_F: 1nF  [0603]  (hidden comment: GRM1885C1H102JA01D)
C221  Cap_F: 10nF  [0603]  (hidden comment: CGA3E2X7R2A103K080AA)
C222  Cap_F: 100nF  [0603]  (hidden comment: CGA3E2X7R1H104K080AA)
C223  ValueDisplayed: 10uF  VDC_V: 35V  [0603]  (hidden comment: GRM188R6YA106MA73D)
C224  ValueDisplayed: 10uF  VDC_V: 35V  [0603]  (hidden comment: GRM188R6YA106MA73D)
C225  ValueDisplayed: 10uF  VDC_V: 35V  [0603]  (hidden comment: GRM188R6YA106MA73D)
C226  ValueDisplayed: 10µF  [1206_190]  (hidden comment: CGA5L1X7R1H106K160AC)
C227  Cap_F: 10nF  [0603]  (hidden comment: CGA3E2X7R2A103K080AA)
C228  ValueDisplayed: 10µF  [1206_190]  (hidden comment: CGA5L1X7R1H106K160AC)
C229  Cap_F: 1µF  [0603]  (hidden comment: CGA3E1X7R1V105K080AC)
C230  ValueDisplayed: 10uF  [1210_270]  (hidden comment: GRM32ER71H106KA12L)
C231  ValueDisplayed: 10uF  [1210_270]  (hidden comment: GRM32ER71H106KA12L)
C232  ValueDisplayed: 10uF  [1210_270]  (hidden comment: GRM32ER71H106KA12L)
C233  Cap_F: 1µF  [0805_HV]  (hidden comment: CGA4J3X7R1H105K125AB)
C234  Cap_F: 100nF  [0603]  (hidden comment: CGA3E2X7R1H104K080AA)
C235  ValueDisplayed: 100pF  [0603]  (hidden comment: CGA3E2NP01H101J080AA)
C236  Cap_F: 68nF  [0603]  (hidden comment: CGA3E2X7R1H683K080AA)
C237  ValueDisplayed: 0.047uF  [0603]  (hidden comment: CGA3E2X7R1H473K080AA)
C238  ValueDisplayed: 220pF  [0603]  (hidden comment: GCM1885C2A221JA16D)
C239  ValueDisplayed: 0.22uF  [0603]  (hidden comment: GCM188R71E224KA55D)
D202  PMEG060V100EPDZ  [SOT1289]
L200  value 47uH  [MSD1514]  (hidden comment: MSD1514-473MEB)
NT200  Net-Tie  [Net-Tie_10mil]  (value not drawn)  (net tie, no BOM)
R235  ValueDisplayed: 100k  [0603]  (hidden comment: CRCW0603100KFKEA)
R236  ValueDisplayed: 78.7k  [0603]  (hidden comment: CRCW060378K7FKEA)
R237  ValueDisplayed: 15.0k  [0603]  (hidden comment: CRCW060315K0FKEA)
R238  ValueDisplayed: 5.11k  [0603]  (hidden comment: CRCW06035K11FKEA)
R239  ValueDisplayed: 5.36k  [0603]  (hidden comment: CRCW06035K36FKEA)
R240  ValueDisplayed: 20.0k  [0603]  (hidden comment: CRCW060320K0FKEA)
R241  ValueDisplayed: 3.01k  [0603]  (hidden comment: CRCW06033K01FKEA)
R242  ValueDisplayed: 10.0  [1210]  (hidden comment: CRCW121010R0FKEAHP)
R243  ValueDisplayed: 34.8k  [0603]  (hidden comment: CRCW060334K8FKEA)
R244  ValueDisplayed: 5.23k  [0603]  (hidden comment: CRCW06035K23FKEA)
R245  ValueDisplayed: 24.9k  [0603]  (hidden comment: CRCW060324K9FKEA)
R246  ValueDisplayed: 121k  [0603]  (hidden comment: CRCW0603121KFKEA)
R247  ValueDisplayed: 22.6k  [0603]  (hidden comment: CRCW060322K6FKEA)
R248  ValueDisplayed: 5.49k  [0603]  (hidden comment: CRCW06035K49FKEA)
R249  ValueDisplayed: 49.9k  [0603]  (hidden comment: CRCW060349K9FKEA)
R250  ValueDisplayed: 61.9k  [0603]  (hidden comment: CRCW060361K9FKEA)
R251  ValueDisplayed: 2.00k  [0603]  (hidden comment: CRCW06032K00FKEA)
TP200  5015  [Testpoint_Keystone_Miniature]  (value not drawn)
TP201  RCU-0C  [TE_RCU]  (value not drawn)
TP202  RCU-0C  [TE_RCU]  (value not drawn)
U201  TPS7B6933QDBVRQ1  [DBV0005A_N]
U202  LM74202QPWPRQ1  [PWP0016J_N]
U203  LM5158QRTERQ1  [RTE0016K-MFG]

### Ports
+3.3V_H, +12V_H, +24V_H, GND, Power_EN_LoadSW, VIN_12V

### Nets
+3.3V_H: C216.1 C217.1 U201.5(OUT) ; port +3.3V_H
+12V_H: C210.1 C211.1 C212.1 C213.1 C214.1 C215.1 C220.1 C221.1 C222.1 C223.1 C224.1 C225.1 C227.1 L200.1 R235.2 R243.2 U201.1(IN) U202.15(OUT) U202.16(OUT) U203.3(BIAS) ; port +12V_H
+24V_H: C219.1 C230.1 C231.1 C232.1 C233.1 C234.1 D202.3(K) R244.2 TP201.1 ; port +24V_H
AGND_A: C235.2 C238.2 C239.2 NT200.2 R247.1 R248.1 R249.1 R250.1 R251.1 U203.7(AGND)
GND: C208.2 C209.2 C210.2 C211.2 C212.2 C213.2 C214.2 C215.2 C216.2 C217.2 C218.2 C220.2 C221.2 C222.2 C223.2 C224.2 C225.2 C227.2 C229.1 C230.2 C231.2 C232.2 C233.2 C234.2 L200.2 NT200.1 R238.1 R239.1 R240.1 R241.1 TP202.1 U201.3(GND) U201.4(GND) U202.6(MODE) U202.8(GND) U202.9(GND) U202.17(PAD) U203.1(PGND) U203.16(PGND) U203.17(EP) ; port GND
VCC_H: C229.2 R245.2 U203.2(VCC)
VIN_12V: C208.1 C209.1 R236.2 R237.2 U202.1(IN) U202.2(IN) U202.3(UVLO) ; port VIN_12V
FB_HS: C236.2 R246.1 R248.2 U203.9(FB)  [project net FB_HS_2]
Power_EN_LoadSW: R237.1 R241.2 U202.7(~{SHDN}) ; port Power_EN_LoadSW
NetC218_1: C218.1 U202.12(DVDT)
NetC219_2: C219.2 R242.2
NetC226_1: C226.1 C228.1 D202.1(A) D202.2(A) L200.4 R242.1
NetC226_2: C226.2 C228.2 L200.3 TP200.1 U203.13(SW) U203.14(SW)
NetC235_1: C235.1 R243.1 R247.2 U203.6(EN/UVLO/SYNC)
NetC236_1: C236.1 R244.1 R246.2
NetC237_1: C237.1 C238.1 U203.8(COMP)
NetC237_2: C237.2 R251.2
NetC239_1: C239.1 U203.10(SS)
NetR235_1: R235.1 U202.14(~{FLT})
NetR236_1: R236.1 R238.2 U202.5(OVP)
NetR239_2: R239.2 U202.11(ILIM)
NetR240_2: R240.2 U202.10(IMON)
NetR245_1: R245.1 U203.4(PGOOD)
NetR249_2: R249.2 U203.5(RT)
NetR250_2: R250.2 U203.11(MODE)

Not connected (* = marked no-connect by the designer): U201 2(NC)*; U202 4(NC) 13(NC); U203 12(NC)* 15(NC)*

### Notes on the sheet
- High Side Power Rail
- Ideal diode with integrated overvoltage and overcurrent protection
- High-side logic power supply
- Magneto MV (UCC14240-Q1) pre-regulator
- VIN 4 - 32VDC
- VOUT 24VDC

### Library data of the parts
C208 C211-C214 C217 = CMP-0007355-6: CAP, CERM, 10 uF, 35 V, +/- 20%, X5R, 0603; Manufacturer: Murata; TaMin_C: -55°C; Polarized: N; SizeAreaWB_mm2: 4.68; Value1: Unknown; U/M: EA; Value: 10uF; TaMax_C: 85°C; SizeZ_mm: 1; SizeX_mm: 1.6; SizeY_mm: 0.8; SizeArea_mm2: 1.28; Cap_F: 10µF; AEC Category: Q200
C209 C210 C215 C216 = CMP-0007078-4: CAP, CERM, 0.1 uF, 50 V, +/- 10%, X7R, AEC-Q200 Grade 1, 0603; Manufacturer: TDK; TaMin_C: -55°C; ESR_ohm: 29.6m; Polarized: N; SizeAreaWB_mm2: 4.68; Value1: 0.0296 ohm; U/M: EA; Value: 0.1uF; TaMax_C: 125°C; SizeZ_mm: 1; SizeX_mm: 1.6; SizeY_mm: 0.8; SizeArea_mm2: 1.28; AEC Qualified: Y; Cap_F: 100nF; IRMS_A: 971.99mA; AEC Category: Q200
C218 = CMP-0007082-4: CAP, CERM, 0.01 uF, 100 V, +/- 10%, X7R, AEC-Q200 Grade 1, 0603; Manufacturer: TDK; TaMin_C: -55°C; Polarized: N; SizeAreaWB_mm2: 4.68; U/M: EA; Value: 0.01uF; TaMax_C: 125°C; SizeZ_mm: 1; SizeX_mm: 1.6; SizeY_mm: 0.8; SizeArea_mm2: 1.28; AEC Qualified: Y; AEC Category: Q200; ESR_ohm: 0.2354; IRMS_A: 396.995mA; Value1: 0.235428 ohm
C219 = CMP-0006959-4: CAP, CERM, 680 pF, 50 V, +/- 5%, C0G/NP0, 0603; Manufacturer: Kemet; TaMin_C: -55°C; Polarized: N; SizeAreaWB_mm2: 4.68; Value1: Unknown; U/M: EA; Value: 680pF; TaMax_C: 125°C; SizeZ_mm: 1; SizeX_mm: 1.6; SizeY_mm: 0.8; Value2: 50V; SizeArea_mm2: 1.28; AEC Category: Q200
C220 = CMP-0007173-4: CAP, CERM, 1000 pF, 50 V, +/- 5%, C0G/NP0, 0603; Manufacturer: MuRata; TaMin_C: -55°C; Polarized: N; SizeAreaWB_mm2: 4.68; Value1: Unknown; U/M: EA; Value: 1000pF; TaMax_C: 125°C; SizeZ_mm: 1; SizeX_mm: 1.6; SizeY_mm: 0.8; Value2: 50V; SizeArea_mm2: 1.28; AEC Category: Q200
C221 = CMP-0007082-4: CAP, CERM, 0.01 uF, 100 V, +/- 10%, X7R, AEC-Q200 Grade 1, 0603; Manufacturer: TDK; TaMin_C: -55°C; Polarized: N; SizeAreaWB_mm2: 4.68; Value1: 0.235428 ohm; U/M: EA; Value: 0.01uF; TaMax_C: 125°C; SizeZ_mm: 1; SizeX_mm: 1.6; SizeY_mm: 0.8; Value2: 100V; SizeArea_mm2: 1.28; AEC Qualified: Y; AEC Category: Q200; ESR_ohm: 0.2354; IRMS_A: 396.995mA
C222 C234 = CMP-0007078-4: CAP, CERM, 0.1 uF, 50 V, +/- 10%, X7R, AEC-Q200 Grade 1, 0603; Manufacturer: TDK; TaMin_C: -55°C; ESR_ohm: 29.6m; Polarized: N; SizeAreaWB_mm2: 4.68; Value1: 0.0296 ohm; U/M: EA; Value: 0.1uF; TaMax_C: 125°C; SizeZ_mm: 1; SizeX_mm: 1.6; SizeY_mm: 0.8; Value2: 50V; SizeArea_mm2: 1.28; AEC Qualified: Y; IRMS_A: 971.99mA; AEC Category: Q200
C223-C225 = CMP-0007355-6: CAP, CERM, 10 uF, 35 V, +/- 20%, X5R, 0603; Manufacturer: Murata; TaMax_C: 85°C; Value1: Unknown; TaMin_C: -55°C; Value: 10uF; SizeZ_mm: 1; SizeArea_mm2: 1.28; AEC Category: Q200; Cap_F: 10µF; SizeY_mm: 0.8; AEC Qualified: N; SizeX_mm: 1.6; SizeAreaWB_mm2: 4.68; U/M: EA
C226 C228 = CMP-0085950-1: CAP, CERM, 10 µF, 50 V,+/- 10%, X7R, AEC-Q200 Grade 1, 1206; Manufacturer: TDK; SizeZ_mm: 1.9; Value: 10uF; Value2: 50V; Cap_Case: 1206; AEC Grade: 1; TaMin_C: -55°C; U/M: EA; SizeArea_mm2: 5.12; TaMax_C: 125°C; AEC Qualified: Y; AEC Category: Q200; SizeX_mm: 3.2; SizeY_mm: 1.6; Polarized: N; SizeAreaWB_mm2: 10.92
C227 = CMP-0007082-4: CAP, CERM, 0.01 uF, 100 V, +/- 10%, X7R, AEC-Q200 Grade 1, 0603; Manufacturer: TDK; TaMin_C: -55°C; Polarized: N; SizeAreaWB_mm2: 4.68; Value1: 0.235428 ohm; U/M: EA; Value: 0.01uF; TaMax_C: 125°C; SizeZ_mm: 1; SizeX_mm: 1.6; Value2: 100V; SizeArea_mm2: 1.28; AEC Qualified: Y; AEC Category: Q200; SizeY_mm: 0.8; ESR_ohm: 0.2354; IRMS_A: 396.995mA
C229 = CMP-0007067-4: CAP, CERM, 1 uF, 35 V, +/- 10%, X7R, AEC-Q200 Grade 1, 0603; Manufacturer: TDK; TaMin_C: -55°C; ESR_ohm: 5.522m; Polarized: N; SizeAreaWB_mm2: 4.68; Value1: 0.005522 ohm; U/M: EA; Value: 1uF; TaMax_C: 125°C; SizeZ_mm: 1; SizeX_mm: 1.6; SizeY_mm: 0.8; Value2: 35V; SizeArea_mm2: 1.28; AEC Qualified: Y; IRMS_A: 2.2162A; AEC Category: Q200
C230-C232 = CMP-0009226-3: CAP, CERM, 10 uF, 50 V, +/- 10%, X7R, 1210; Manufacturer: MuRata; TaMin_C: -55°C; Polarized: N; SizeAreaWB_mm2: 14.7; Value1: Unknown; U/M: EA; Value: 10uF; TaMax_C: 125°C; SizeZ_mm: 2.7; SizeX_mm: 3.2; SizeY_mm: 2.5; Cap_Case: 1210; Value2: 50V; SizeArea_mm2: 8; Cap_F: 10µF; AEC Category: Q200
C233 = CMP-0007976-2: CAP, CERM, 1 uF, 50 V, +/- 10%, X7R, AEC-Q200 Grade 1, 0805; Manufacturer: TDK; TaMin_C: -55°C; Polarized: N; SizeAreaWB_mm2: 6.75; Value1: 0.008782 ohm; U/M: EA; Value: 1uF; TaMax_C: 125°C; SizeZ_mm: 1.45; SizeX_mm: 2; SizeY_mm: 1.25; Cap_Case: 0805; Value2: 50V; SizeArea_mm2: 2.5; AEC Qualified: Y; AEC Grade: 1; AEC Category: Q200; ESR_ohm: 8.782m; IRMS_A: 2.2049A
C235 = CMP-0007075-4: CAP, CERM, 100 pF, 50 V, +/- 5%, C0G/NP0, AEC-Q200 Grade 0, 0603; Manufacturer: TDK; TaMin_C: -55°C; Polarized: N; SizeAreaWB_mm2: 4.68; Value1: Unknown; U/M: EA; Value: 100pF; TaMax_C: 150°C; SizeZ_mm: 1; SizeX_mm: 1.6; SizeY_mm: 0.8; Value2: 50V; SizeArea_mm2: 1.28; AEC Qualified: Y; AEC Grade: 0; AEC Category: Q200
C236 = CMP-0007080-5: CAP, CERM, 0.068 uF, 50 V, +/- 10%, X7R, AEC-Q200 Grade 1, 0603; Manufacturer: TDK; TaMin_C: -55°C; Polarized: N; SizeAreaWB_mm2: 4.68; Value1: 0.035979 ohm; U/M: EA; TaMax_C: 125°C; SizeZ_mm: 1; SizeX_mm: 1.6; SizeY_mm: 0.8; Value2: 50V; SizeArea_mm2: 1.28; AEC Qualified: Y; AEC Category: Q200; ESR_ohm: 35.979m; IRMS_A: 886.483mA
C237 = CMP-0007079-4: CAP, CERM, 0.047 uF, 50 V, +/- 10%, X7R, AEC-Q200 Grade 1, 0603; Manufacturer: TDK; TaMin_C: -55°C; ESR_ohm: 49.007m; Polarized: N; SizeAreaWB_mm2: 4.68; Value1: 0.049007 ohm; U/M: EA; TaMax_C: 125°C; SizeZ_mm: 1; SizeX_mm: 1.6; SizeY_mm: 0.8; Value2: 50V; SizeArea_mm2: 1.28; AEC Qualified: Y; Cap_F: 47nF; IRMS_A: 767.528mA; AEC Category: Q200
C238 = CMP-0860912-1: CAP, CERM, 220 pF, 100 V,+/- 5%, C0G/NP0, AEC-Q200 Grade 1, 0603; Manufacturer: MuRata; TaMin_C: -55°C; Polarized: N; SizeAreaWB_mm2: 4.68; U/M: EA; Value: 220pF; TaMax_C: 125°C; SizeZ_mm: 1; SizeX_mm: 1.6; SizeY_mm: 0.8; Value2: 100V; SizeArea_mm2: 1.28; AEC Qualified: Y; AEC Category: Q200
C239 = CMP-0007140-4: CAP, CERM, 0.22 uF, 25 V, +/- 10%, X7R, AEC-Q200 Grade 1, 0603; Manufacturer: MuRata; TaMin_C: -55°C; Polarized: N; SizeAreaWB_mm2: 4.68; Value1: Unknown; U/M: EA; Value: 0.22uF; TaMax_C: 125°C; SizeZ_mm: 1; SizeX_mm: 1.6; Value2: 25V; SizeArea_mm2: 1.28; AEC Qualified: Y; Cap_F: 220nF; AEC Category: Q200; SizeY_mm: 0.8
D202 = CMP-0028984-3: Diode, Schottky, 60 V, 10 A, AEC-Q101, CFP15; Manufacturer: Nexperia; Io_A: 10A; SizeAreaWB_mm2: 53.55; Vr_V: 60V; TJmax_C: 175°C; Value: 60V; SizeZ_mm: 0.82; SizeX_mm: 6.5; SizeY_mm: 4.3; Vf_V: 560mV; Value2: 0.56V; SizeArea_mm2: 27.95; AEC Qualified: Y; AEC Category: Q101
L200 = CMP-0080788-1: Coupled inductor, 47 µH, 7.5 A, 0.065 ohm, SMD; Manufacturer: Coilcraft; SizeAreaWB_mm2: 289; DCR_ohm: 65m; SizeZ_mm: 14.2; SizeX_mm: 15; SizeArea_mm2: 225; Ind_H: 47µH; AEC Qualified: N; AEC Category: Q200
NT200 = CMP-0078142-6: Single point connection between nets.
R235 = CMP-0021990-4: RES, 100 k, 1%, 0.1 W, AEC-Q200 Grade 0, 0603; Manufacturer: Vishay-Dale; Power_W: 100mW; TempCo: 100 ppm/C; Value: 100k; EIA_Code: E96; SizeX_mm: 1.6; SizeY_mm: 0.8; SizeZ_mm: 1; Value2: 0.1W; SizeArea_mm2: 1.28; AEC Qualified: Y; VDC_V: 75V; AEC Category: Q200; AEC Grade: 0
R236 = CMP-0022597-4: RES, 78.7 k, 1%, 0.1 W, AEC-Q200 Grade 0, 0603; Manufacturer: Vishay-Dale; Power_W: 100mW; TempCo: 100 ppm/C; Value_Code: 78k7; Value: 78.7k; EIA_Code: E96; SizeX_mm: 1.6; SizeY_mm: 0.8; SizeZ_mm: 1; Value2: 0.1W; SizeArea_mm2: 1.28; AEC Qualified: Y; VDC_V: 75V; AEC Category: Q200; AEC Grade: 0
R237 = CMP-0022066-4: RES, 15.0 k, 1%, 0.1 W, AEC-Q200 Grade 0, 0603; Manufacturer: Vishay-Dale; Value: 15.0k; Res_ohm: 15k; Value_Code: 15k0; Power_W: 100mW; Value2: 0.1W; VDC_V: 75V; TempCo: 100 ppm/C; SizeArea_mm2: 1.28; SizeX_mm: 1.6; SizeY_mm: 0.8; SizeZ_mm: 1; EIA_Code: E96; AEC Category: Q200; AEC Qualified: Y; AEC Grade: 0
R238 = CMP-0022509-4: RES, 5.11 k, 1%, 0.1 W, AEC-Q200 Grade 0, 0603; Manufacturer: Vishay-Dale; Power_W: 100mW; TempCo: 100 ppm/C; Value_Code: 5k11; Value: 5.11k; EIA_Code: E96; SizeX_mm: 1.6; SizeY_mm: 0.8; SizeZ_mm: 1; Value2: 0.1W; SizeArea_mm2: 1.28; AEC Qualified: Y; VDC_V: 75V; AEC Category: Q200; AEC Grade: 0
R239 = CMP-0022511-4: RES, 5.36 k, 1%, 0.1 W, AEC-Q200 Grade 0, 0603; Manufacturer: Vishay-Dale; Power_W: 100mW; TempCo: 100 ppm/C; Value_Code: 5k36; Value: 5.36k; EIA_Code: E96; SizeX_mm: 1.6; SizeY_mm: 0.8; SizeZ_mm: 1; Value2: 0.1W; SizeArea_mm2: 1.28; AEC Qualified: Y; VDC_V: 75V; AEC Category: Q200; AEC Grade: 0
R240 = CMP-0022204-4: RES, 20.0 k, 1%, 0.1 W, AEC-Q200 Grade 0, 0603; Manufacturer: Vishay-Dale; Power_W: 100mW; TempCo: 100 ppm/C; Value_Code: 20k0; Value: 20.0k; EIA_Code: E96; Res_ohm: 20k; SizeX_mm: 1.6; SizeY_mm: 0.8; SizeZ_mm: 1; Value2: 0.1W; SizeArea_mm2: 1.28; AEC Qualified: Y; VDC_V: 75V; AEC Category: Q200; AEC Grade: 0
R241 = CMP-0022371-4: RES, 3.01 k, 1%, 0.1 W, AEC-Q200 Grade 0, 0603; Manufacturer: Vishay-Dale; Value: 3.01k; Value_Code: 3k01; Power_W: 100mW; Value2: 0.1W; VDC_V: 75V; TempCo: 100 ppm/C; SizeArea_mm2: 1.28; SizeX_mm: 1.6; SizeY_mm: 0.8; SizeZ_mm: 1; EIA_Code: E96; AEC Category: Q200; AEC Qualified: Y; AEC Grade: 0
R242 = CMP-0015019-3: RES, 10.0, 1%, 0.75 W, AEC-Q200 Grade 0, 1210; Manufacturer: Vishay-Dale; Power_W: 750mW; TempCo: 100 ppm/C; SizeAreaWB_mm2: 14.7; Value_Code: 10R0; Value: 10.0; EIA_Code: E96; Res_ohm: 10; SizeX_mm: 3.2; SizeY_mm: 2.5; SizeZ_mm: 1.35; Value2: 0.75W; SizeArea_mm2: 8; AEC Qualified: Y; AEC Grade: 0; AEC Category: Q200
R243 = CMP-0022347-4: RES, 34.8 k, 1%, 0.1 W, AEC-Q200 Grade 0, 0603; Manufacturer: Vishay-Dale; Power_W: 100mW; TempCo: 100 ppm/C; Value_Code: 34k8; Value: 34.8k; EIA_Code: E96; SizeX_mm: 1.6; SizeY_mm: 0.8; SizeZ_mm: 1; Value2: 0.1W; SizeArea_mm2: 1.28; AEC Qualified: Y; VDC_V: 75V; AEC Category: Q200; AEC Grade: 0
R244 = CMP-0022510-4: RES, 5.23 k, 1%, 0.1 W, AEC-Q200 Grade 0, 0603; Manufacturer: Vishay-Dale; Power_W: 100mW; TempCo: 100 ppm/C; Value_Code: 5k23; Value: 5.23k; EIA_Code: E96; SizeX_mm: 1.6; SizeY_mm: 0.8; SizeZ_mm: 1; Value2: 0.1W; SizeArea_mm2: 1.28; AEC Qualified: Y; VDC_V: 75V; AEC Category: Q200; AEC Grade: 0
R245 = CMP-0022237-4: RES, 24.9 k, 1%, 0.1 W, AEC-Q200 Grade 0, 0603; Manufacturer: Vishay-Dale; Power_W: 100mW; TempCo: 100 ppm/C; Value_Code: 24k9; Value: 24.9k; EIA_Code: E96; SizeX_mm: 1.6; SizeY_mm: 0.8; SizeZ_mm: 1; Value2: 0.1W; SizeArea_mm2: 1.28; AEC Qualified: Y; VDC_V: 75V; AEC Category: Q200; AEC Grade: 0
R246 = CMP-0022024-4: RES, 121 k, 1%, 0.1 W, AEC-Q200 Grade 0, 0603; Manufacturer: Vishay-Dale; Power_W: 100mW; TempCo: 100 ppm/C; Value: 121k; EIA_Code: E96; SizeX_mm: 1.6; SizeY_mm: 0.8; SizeZ_mm: 1; Value2: 0.1W; SizeArea_mm2: 1.28; AEC Qualified: Y; VDC_V: 75V; AEC Category: Q200; AEC Grade: 0
R247 = CMP-0022221-4: RES, 22.6 k, 1%, 0.1 W, AEC-Q200 Grade 0, 0603; Manufacturer: Vishay-Dale; Power_W: 100mW; TempCo: 100 ppm/C; Value_Code: 22k6; Value: 22.6k; EIA_Code: E96; SizeX_mm: 1.6; SizeY_mm: 0.8; SizeZ_mm: 1; Value2: 0.1W; SizeArea_mm2: 1.28; AEC Qualified: Y; VDC_V: 75V; AEC Category: Q200; AEC Grade: 0
R248 = CMP-0022512-4: RES, 5.49 k, 1%, 0.1 W, AEC-Q200 Grade 0, 0603; Manufacturer: Vishay-Dale; Power_W: 100mW; TempCo: 100 ppm/C; Value_Code: 5k49; Value: 5.49k; EIA_Code: E96; SizeX_mm: 1.6; SizeY_mm: 0.8; SizeZ_mm: 1; Value2: 0.1W; SizeArea_mm2: 1.28; AEC Qualified: Y; VDC_V: 75V; AEC Category: Q200; AEC Grade: 0
R249 = CMP-0022447-4: RES, 49.9 k, 1%, 0.1 W, AEC-Q200 Grade 0, 0603; Manufacturer: Vishay-Dale; Power_W: 100mW; TempCo: 100 ppm/C; Value_Code: 49k9; Value: 49.9k; EIA_Code: E96; SizeX_mm: 1.6; SizeY_mm: 0.8; SizeZ_mm: 1; Value2: 0.1W; SizeArea_mm2: 1.28; AEC Qualified: Y; VDC_V: 75V; AEC Category: Q200; AEC Grade: 0
R250 = CMP-0022536-4: RES, 61.9 k, 1%, 0.1 W, AEC-Q200 Grade 0, 0603; Manufacturer: Vishay-Dale; Power_W: 100mW; TempCo: 100 ppm/C; Value_Code: 61k9; Value: 61.9k; EIA_Code: E96; SizeX_mm: 1.6; SizeY_mm: 0.8; SizeZ_mm: 1; Value2: 0.1W; SizeArea_mm2: 1.28; AEC Qualified: Y; VDC_V: 75V; AEC Category: Q200; AEC Grade: 0
R251 = CMP-0022268-4: RES, 2.00 k, 1%, 0.1 W, AEC-Q200 Grade 0, 0603; Manufacturer: Vishay-Dale; Power_W: 100mW; TempCo: 100 ppm/C; Value_Code: 2k00; Value: 2.00k; Res_ohm: 2k; SizeX_mm: 1.6; SizeY_mm: 0.8; SizeZ_mm: 1; Value2: 0.1W; SizeArea_mm2: 1.28; AEC Qualified: Y; VDC_V: 75V; AEC Grade: 0; AEC Category: Q200; EIA_Code: E96
TP200 = CMP-0055152-2: Test Point, Miniature, SMT; Manufacturer: Keystone Electronics; CNHeader: FALSE; Green_Lifecycle: Active; Green_REACh: Passed; CT: TRUE
TP201 TP202 = CMP-0067620-1: PC Test Point, SMT; Manufacturer: TE Connectivity
U201 = CMP-0079175-1: Automotive High-Voltage Ultralow-IQ Low-Dropout Regulator, DBV0005A (SOT-23-5); Alternate Manufacturer: Texas Instruments; SizeAreaWB_mm2: 14.82; SizeZ_mm: 1.45; SizeX_mm: 2.8; SizeY_mm: 2.9; SizeArea_mm2: 8.12; CompType: IC; AEC Qualified: Y; AEC Category: Q200
U202 = CMP-0086311-1: 40V, 2A Integrated Ideal Diode with Over-Voltage & Over-Current protection, PWP0016J (HTSSOP-16); Alternate Manufacturer: Texas Instruments; CompType: IC; SizeAreaWB_mm2: 58.8; AEC Qualified: N; SizeZ_mm: 1.2; SizeY_mm: 5; AEC Category: Q200; SizeX_mm: 6.4; SizeArea_mm2: 32
U203 = CMP-0091836-5: 2.2-MHz Wide VIN 85-V Boost/Sepic/Flyback Converter with Dual Random Spread Spectrum; Manufacturer: Texas Instruments; Switching Frequency: 100-2200kHz; AEC Qualified: Yes; AEC Grade: Grade 1; Max Supply Voltage: 60V; Number Of Outputs: 1; Output Type: AdjustableProgrammable; TaMax_C: +125°C; Nominal Supply Current: 670uA; CompType: IC; Switching Topology: Boost,Flyback; AEC Category: Q200; Output Voltage: 83V; Standoff Height: 0mm; TJmax_C: +150°C; Max Duty Cycle: 96%; TaMin_C: -40°C; SizeZ_mm: 0.8mm; Min Supply Voltage: 1.5V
